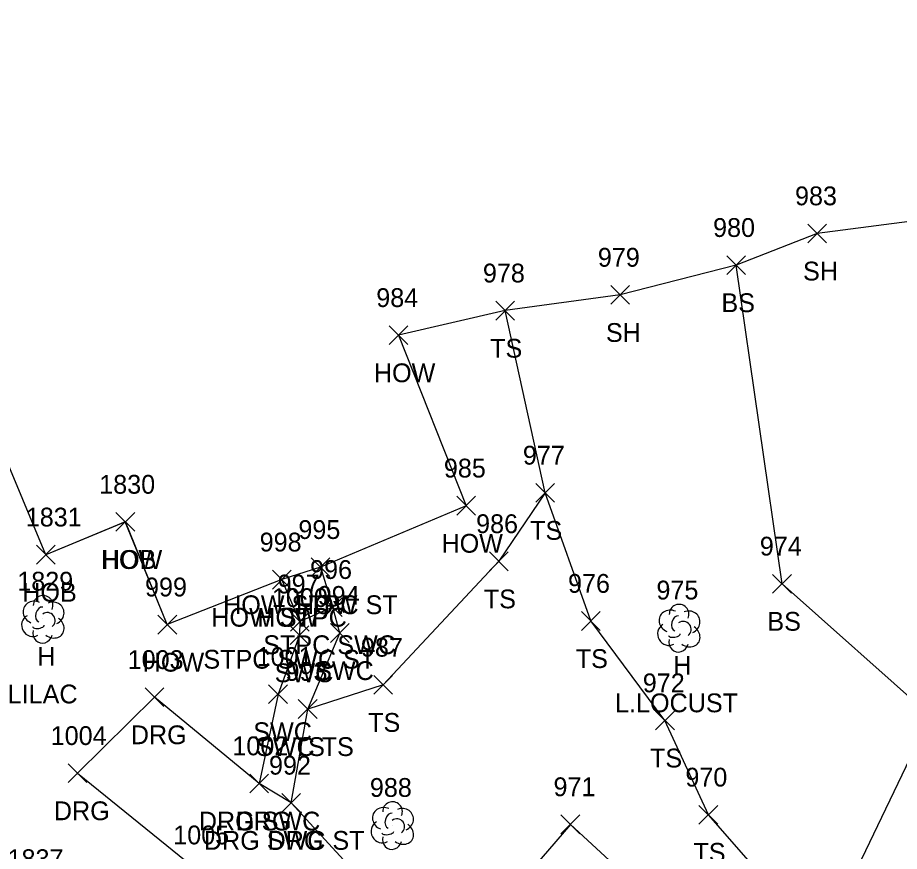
# Model space of a CAD drawing. Extents: x 1443590 to 1445966, y 578314 to 580556.
# Drawn here: x 1445218.3 to 1445312.1, y 579160.6 to 579249.3 of the extents above; entities that cross this region are included whole.
import ezdxf

# ---------------------------------------------------------------- set-up
doc = ezdxf.new("R2010")
doc.units = 0
for name, color, linetype in [('L_A', 7, 'Continuous'), ('L_C', 7, 'Continuous'), ('L_I', 7, 'Continuous'), ('L_TIC', 7, 'Continuous'), ('LAWA', 7, 'Continuous'), ('LBC', 7, 'Continuous'), ('LBF', 7, 'Continuous'), ('LELB', 7, 'Continuous'), ('LSOGP', 7, 'Continuous'), ('LTD', 7, 'Continuous'), ('R_A', 7, 'Continuous'), ('R_I', 7, 'Continuous'), ('R_TIC', 7, 'Continuous'), ('RDG', 7, 'Continuous'), ('RSW', 7, 'Continuous')]:
    doc.layers.add(name, color=color, linetype=linetype)

msp = doc.modelspace()

# ---------------------------------------------------------------- linework, layer by layer
at = {"layer": 'L_TIC'}
for points in [[(1445302.405, 579225.367), (1445304.405, 579227.367)], [(1445304.405, 579225.367), (1445302.405, 579227.367)], [(1445293.774, 579221.999), (1445295.774, 579223.999)], [(1445295.774, 579221.999), (1445293.774, 579223.999)], [(1445281.438, 579218.831), (1445283.438, 579220.831)], [(1445283.438, 579218.831), (1445281.438, 579220.831)], [(1445269.202, 579217.156), (1445271.202, 579219.156)], [(1445271.202, 579217.156), (1445269.202, 579219.156)], [(1445257.859, 579214.542), (1445259.859, 579216.542)], [(1445259.859, 579214.542), (1445257.859, 579216.542)], [(1445273.455, 579197.777), (1445275.455, 579199.777)], [(1445275.455, 579197.777), (1445273.455, 579199.777)], [(1445273.455, 579197.777), (1445275.455, 579199.777)], [(1445275.455, 579197.777), (1445273.455, 579199.777)], [(1445265.05, 579196.404), (1445267.05, 579198.404)], [(1445267.05, 579196.404), (1445265.05, 579198.404)], [(1445228.803, 579194.68), (1445230.803, 579196.68)], [(1445230.803, 579194.68), (1445228.803, 579196.68)], [(1445228.803, 579194.68), (1445230.803, 579196.68)], [(1445230.803, 579194.68), (1445228.803, 579196.68)], [(1445220.335, 579191.193), (1445222.335, 579193.193)], [(1445222.335, 579191.193), (1445220.335, 579193.193)], [(1445268.53, 579190.488), (1445270.53, 579192.488)], [(1445270.53, 579190.488), (1445268.53, 579192.488)], [(1445249.572, 579189.867), (1445251.572, 579191.867)], [(1445251.572, 579189.867), (1445249.572, 579191.867)], [(1445249.572, 579189.867), (1445251.572, 579191.867)], [(1445251.572, 579189.867), (1445249.572, 579191.867)], [(1445245.455, 579188.537), (1445247.455, 579190.537)], [(1445247.455, 579188.537), (1445245.455, 579190.537)], [(1445245.455, 579188.537), (1445247.455, 579190.537)], [(1445247.455, 579188.537), (1445245.455, 579190.537)], [(1445298.66, 579188.103), (1445300.66, 579190.103)], [(1445300.66, 579188.103), (1445298.66, 579190.103)], [(1445250.87, 579185.613), (1445252.87, 579187.613)], [(1445252.87, 579185.613), (1445250.87, 579187.613)], [(1445247.367, 579184.068), (1445249.367, 579186.068)], [(1445249.367, 579184.068), (1445247.367, 579186.068)], [(1445278.312, 579184.139), (1445280.312, 579186.139)], [(1445280.312, 579184.139), (1445278.312, 579186.139)], [(1445233.264, 579183.753), (1445235.264, 579185.753)], [(1445235.264, 579183.753), (1445233.264, 579185.753)], [(1445256.226, 579177.346), (1445258.226, 579179.346)], [(1445258.226, 579177.346), (1445256.226, 579179.346)], [(1445248.203, 579174.774), (1445250.203, 579176.774)], [(1445250.203, 579174.774), (1445248.203, 579176.774)], [(1445286.209, 579173.556), (1445288.209, 579175.556)], [(1445288.209, 579173.556), (1445286.209, 579175.556)], [(1445290.828, 579163.526), (1445292.828, 579165.526)], [(1445292.828, 579163.526), (1445290.828, 579165.526)]]:
    msp.add_lwpolyline(points, dxfattribs=at)
at = {"layer": 'LAWA'}
msp.add_lwpolyline([(1445372.27, 579155.454), (1445350.04, 579149.983), (1445331.313, 579147.354), (1445306.91, 579136.985), (1445292.898, 579134.144), (1445303.827, 579150.823), (1445315.451, 579175.055), (1445318.511, 579203.194), (1445322.238, 579228.808)], dxfattribs=at)
at = {"layer": 'LBC'}
for points in [[(1445258.859, 579215.542), (1445266.05, 579197.404), (1445250.572, 579190.867), (1445246.455, 579189.537), (1445234.264, 579184.753), (1445229.803, 579195.68)], [(1445229.803, 579195.68), (1445221.335, 579192.193), (1445215.097, 579207.101)]]:
    msp.add_lwpolyline(points, dxfattribs=at)
at = {"layer": 'LBF'}
msp.add_lwpolyline([(1445250.572, 579190.867), (1445251.87, 579186.613), (1445248.367, 579185.068), (1445246.455, 579189.537)], dxfattribs=at)
at = {"layer": 'LELB'}
for points in [[(1445315.451, 579175.055), (1445299.66, 579189.103), (1445294.774, 579222.999)], [(1445274.455, 579198.777), (1445270.202, 579218.156)], [(1445303.827, 579150.823), (1445291.828, 579164.526), (1445287.209, 579174.556), (1445279.312, 579185.139), (1445274.455, 579198.777), (1445269.53, 579191.488), (1445257.226, 579178.346), (1445249.203, 579175.774)]]:
    msp.add_lwpolyline(points, dxfattribs=at)
at = {"layer": 'LSOGP'}
msp.add_lwpolyline([(1445322.239, 579228.805), (1445303.405, 579226.368), (1445294.772, 579223.005), (1445282.438, 579219.832), (1445270.202, 579218.157), (1445258.858, 579215.543), (1445266.05, 579197.405), (1445250.568, 579190.872), (1445246.454, 579189.539), (1445234.26, 579184.757), (1445229.801, 579195.675), (1445221.335, 579192.193), (1445215.096, 579207.096), (1445165.858, 579228.133), (1445139.649, 579247.343), (1445128.368, 579263.152), (1445122.129, 579272.364)], dxfattribs=at)
at = {"layer": 'LTD'}
for p, q in [((1445221.009, 579185.372), (1445221.009, 579185.372)), ((1445221.009, 579185.372), (1445221.009, 579185.372)), ((1445288.663, 579184.429), (1445288.663, 579184.429)), ((1445288.663, 579184.429), (1445288.663, 579184.429)), ((1445258.18, 579163.428), (1445258.18, 579163.428)), ((1445258.18, 579163.428), (1445258.18, 579163.428))]:
    msp.add_line(p, q, dxfattribs=at)
for centre in [(1445221.056, 579186.806), (1445288.71, 579185.863), (1445258.227, 579164.862)]:
    msp.add_arc(centre, 1.047, 335.52715, 180.95627, dxfattribs=at)
for centre, major_axis, ratio, start_param, end_param in [((1445220.217, 579186.038), (1.21, -0.512), 0.895232, 1.570796, 4.712389), ((1445222.051, 579185.955), (-1.141, -0.483), 0.949671, 1.570796, 4.712389), ((1445220.801, 579185.83), (-0.208, -0.792), 0.645439, 3.141593, 6.283185), ((1445221.509, 579185.205), (-0.5, 0.667), 0.989748, 3.141593, 6.283185), ((1445287.871, 579185.096), (1.21, -0.512), 0.895232, 1.570796, 4.712389), ((1445289.704, 579185.013), (-1.141, -0.483), 0.949671, 1.570796, 4.712389), ((1445219.926, 579184.663), (0.584, -1.042), 0.959034, 3.141593, 6.283185), ((1445222.009, 579184.539), (-1.09, 0.792), 0.841452, 1.570796, 4.712389), ((1445288.454, 579184.887), (-0.208, -0.792), 0.645439, 3.141593, 6.283185), ((1445289.163, 579184.263), (-0.5, 0.667), 0.989748, 3.141593, 6.283185), ((1445221.009, 579183.872), (0.265, 1.061), 0.942809, 1.570796, 4.712389), ((1445220.551, 579184.622), (-0.625, -0.083), 0.423636, 0, 3.141593), ((1445287.58, 579183.721), (0.584, -1.042), 0.959034, 3.141593, 6.283185), ((1445289.663, 579183.596), (-1.09, 0.792), 0.841452, 1.570796, 4.712389), ((1445288.663, 579182.929), (0.265, 1.061), 0.942809, 1.570796, 4.712389), ((1445288.205, 579183.679), (-0.625, -0.083), 0.423636, 0, 3.141593), ((1445257.388, 579164.094), (1.21, -0.512), 0.895232, 1.570796, 4.712389), ((1445259.222, 579164.011), (-1.141, -0.483), 0.949671, 1.570796, 4.712389), ((1445257.972, 579163.886), (-0.208, -0.792), 0.645439, 3.141593, 6.283185), ((1445257.097, 579162.719), (0.584, -1.042), 0.959034, 3.141593, 6.283185), ((1445258.68, 579163.261), (-0.5, 0.667), 0.989748, 3.141593, 6.283185), ((1445259.18, 579162.594), (-1.09, 0.792), 0.841452, 1.570796, 4.712389), ((1445257.722, 579162.678), (-0.625, -0.083), 0.423636, 0, 3.141593), ((1445258.18, 579161.928), (0.265, 1.061), 0.942809, 1.570796, 4.712389)]:
    msp.add_ellipse(centre, major_axis=major_axis, ratio=ratio, start_param=start_param, end_param=end_param, dxfattribs=at)
at = {"layer": 'R_TIC'}
for points in [[(1445250.87, 579185.613), (1445252.87, 579187.613)], [(1445252.87, 579185.613), (1445250.87, 579187.613)], [(1445247.367, 579184.068), (1445249.367, 579186.068)], [(1445249.367, 579184.068), (1445247.367, 579186.068)], [(1445251.63, 579182.859), (1445253.63, 579184.859)], [(1445253.63, 579182.859), (1445251.63, 579184.859)], [(1445247.326, 579182.624), (1445249.326, 579184.624)], [(1445249.326, 579182.624), (1445247.326, 579184.624)], [(1445245.048, 579176.357), (1445247.048, 579178.357)], [(1445247.048, 579176.357), (1445245.048, 579178.357)], [(1445231.898, 579176.03), (1445233.898, 579178.03)], [(1445233.898, 579176.03), (1445231.898, 579178.03)], [(1445248.203, 579174.774), (1445250.203, 579176.774)], [(1445250.203, 579174.774), (1445248.203, 579176.774)], [(1445223.709, 579167.946), (1445225.709, 579169.946)], [(1445225.709, 579167.946), (1445223.709, 579169.946)], [(1445243.035, 579166.852), (1445245.035, 579168.852)], [(1445245.035, 579166.852), (1445243.035, 579168.852)], [(1445243.035, 579166.852), (1445245.035, 579168.852)], [(1445245.035, 579166.852), (1445243.035, 579168.852)], [(1445246.445, 579164.796), (1445248.445, 579166.796)], [(1445248.445, 579164.796), (1445246.445, 579166.796)], [(1445246.445, 579164.796), (1445248.445, 579166.796)], [(1445248.445, 579164.796), (1445246.445, 579166.796)], [(1445276.145, 579162.501), (1445278.145, 579164.501)], [(1445278.145, 579162.501), (1445276.145, 579164.501)]]:
    msp.add_lwpolyline(points, dxfattribs=at)
at = {"layer": 'RDG'}
msp.add_lwpolyline([(1445290.54, 579120.697), (1445286.786, 579125.137), (1445282.411, 579132.327), (1445292.725, 579149.141), (1445277.145, 579163.501), (1445263.786, 579148.008), (1445247.445, 579165.796), (1445244.035, 579167.852), (1445232.898, 579177.03), (1445224.709, 579168.946), (1445237.747, 579158.377), (1445246.785, 579149.354), (1445249.553, 579146.241), (1445259.673, 579137.719), (1445262.189, 579129.261), (1445260.436, 579122.719), (1445257.452, 579113.853)], dxfattribs=at)
at = {"layer": 'RSW'}
for points in [[(1445247.445, 579165.796), (1445249.203, 579175.774), (1445252.63, 579183.859), (1445251.87, 579186.613)], [(1445248.367, 579185.068), (1445248.326, 579183.624), (1445246.048, 579177.357), (1445244.035, 579167.852)]]:
    msp.add_lwpolyline(points, dxfattribs=at)

# ---------------------------------------------------------------- texts
at = {"layer": 'L_A'}
for s, p in [('SH', (1445301.893, 579221.367)), ('BS', (1445293.215, 579217.999)), ('SH', (1445280.926, 579214.831)), ('TS', (1445268.612, 579213.156)), ('HOW', (1445256.244, 579210.542)), ('TS', (1445272.865, 579193.777)), ('TS', (1445272.865, 579193.777)), ('HOW', (1445263.436, 579192.404)), ('HOW', (1445227.189, 579190.68)), ('HOB', (1445227.307, 579190.68)), ('HOB', (1445218.839, 579187.193)), ('HOW STPC ST', (1445240.202, 579185.867)), ('HOW', (1445247.958, 579185.867)), ('TS', (1445267.94, 579186.488)), ('HOW STPC', (1445238.951, 579184.537)), ('HOW', (1445243.84, 579184.537)), ('BS', (1445298.101, 579184.103)), ('STPC SWC', (1445244.476, 579181.613)), ('H', (1445220.442, 579180.372)), ('STPC SWC ST', (1445238.107, 579180.068)), ('TS', (1445277.721, 579180.139)), ('HOW', (1445231.65, 579179.753)), ('H', (1445288.096, 579179.429)), ('TS', (1445255.635, 579173.346)), ('TS', (1445247.613, 579170.774)), ('TS', (1445285.618, 579169.556)), ('TS', (1445290.237, 579159.526))]:
    msp.add_text(s, height=2, dxfattribs=at).set_placement(p)
at = {"layer": 'L_C'}
for s, p in [('LILAC', (1445217.285, 579176.372)), ('L.LOCUST', (1445281.899, 579175.429))]:
    msp.add_text(s, height=2, dxfattribs=at).set_placement(p)
at = {"layer": 'L_I'}
for s, p in [('983', (1445301.043, 579229.367)), ('980', (1445292.326, 579225.999)), ('979', (1445280.068, 579222.831)), ('978', (1445267.84, 579221.156)), ('984', (1445256.496, 579218.542)), ('977', (1445272.093, 579201.777)), ('977', (1445272.093, 579201.777)), ('985', (1445263.688, 579200.404)), ('1830', (1445227.024, 579198.68)), ('1830', (1445227.024, 579198.68)), ('1831', (1445219.209, 579195.193)), ('986', (1445267.113, 579194.488)), ('995', (1445248.21, 579193.867)), ('995', (1445248.21, 579193.867)), ('998', (1445244.092, 579192.537)), ('998', (1445244.092, 579192.537)), ('974', (1445297.298, 579192.103)), ('996', (1445249.453, 579189.613)), ('1829', (1445218.309, 579188.372)), ('999', (1445231.894, 579187.753)), ('997', (1445246.005, 579188.068)), ('976', (1445276.894, 579188.139)), ('975', (1445286.301, 579187.429)), ('987', (1445254.864, 579181.346)), ('993', (1445246.841, 579178.774)), ('972', (1445284.847, 579177.556)), ('970', (1445289.379, 579167.526)), ('988', (1445255.818, 579166.428)), ('1837', (1445217.271, 579158.852))]:
    msp.add_text(s, height=2, dxfattribs=at).set_placement(p)
at = {"layer": 'R_A'}
for s, p in [('STPC SWC', (1445244.476, 579181.613)), ('STPC SWC ST', (1445238.107, 579180.068)), ('SWC', (1445245.688, 579178.624)), ('SWC', (1445249.992, 579178.859)), ('DRG', (1445230.386, 579172.03)), ('SWC', (1445243.41, 579172.357)), ('SWC TS', (1445243.707, 579170.774)), ('DRG', (1445222.198, 579163.946)), ('DRG SWC', (1445237.618, 579162.852)), ('DRG', (1445241.523, 579162.852)), ('DRG SWC ST', (1445238.162, 579160.796)), ('DRG', (1445244.934, 579160.796))]:
    msp.add_text(s, height=2, dxfattribs=at).set_placement(p)
at = {"layer": 'R_I'}
for s, p in [('996', (1445249.453, 579189.613)), ('997', (1445246.005, 579188.068)), ('1000', (1445245.389, 579186.624)), ('994', (1445250.268, 579186.859)), ('1003', (1445230.047, 579180.03)), ('1001', (1445243.765, 579180.357)), ('993', (1445246.841, 579178.774)), ('1004', (1445221.859, 579171.946)), ('1002', (1445241.185, 579170.852)), ('1002', (1445241.185, 579170.852)), ('992', (1445245.083, 579168.796)), ('992', (1445245.083, 579168.796)), ('971', (1445275.35, 579166.501)), ('1005', (1445234.897, 579161.377))]:
    msp.add_text(s, height=2, dxfattribs=at).set_placement(p)

doc.saveas('drawing.dxf')
